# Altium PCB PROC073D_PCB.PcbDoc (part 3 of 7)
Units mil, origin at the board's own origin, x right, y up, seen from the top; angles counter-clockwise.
Board outline 2165.35 x 2695.12 mil, 8 copper layers (Top Layer, L2_GND, L3_SIGNAL 1, L4_SIGNAL 2, L5_SIGNAL 3, L6_SIGNAL 4, L7_GND, Bottom Layer), stack 56.1 mil thick; 414 components, 319 nets, 1353 pads, 1669 vias.
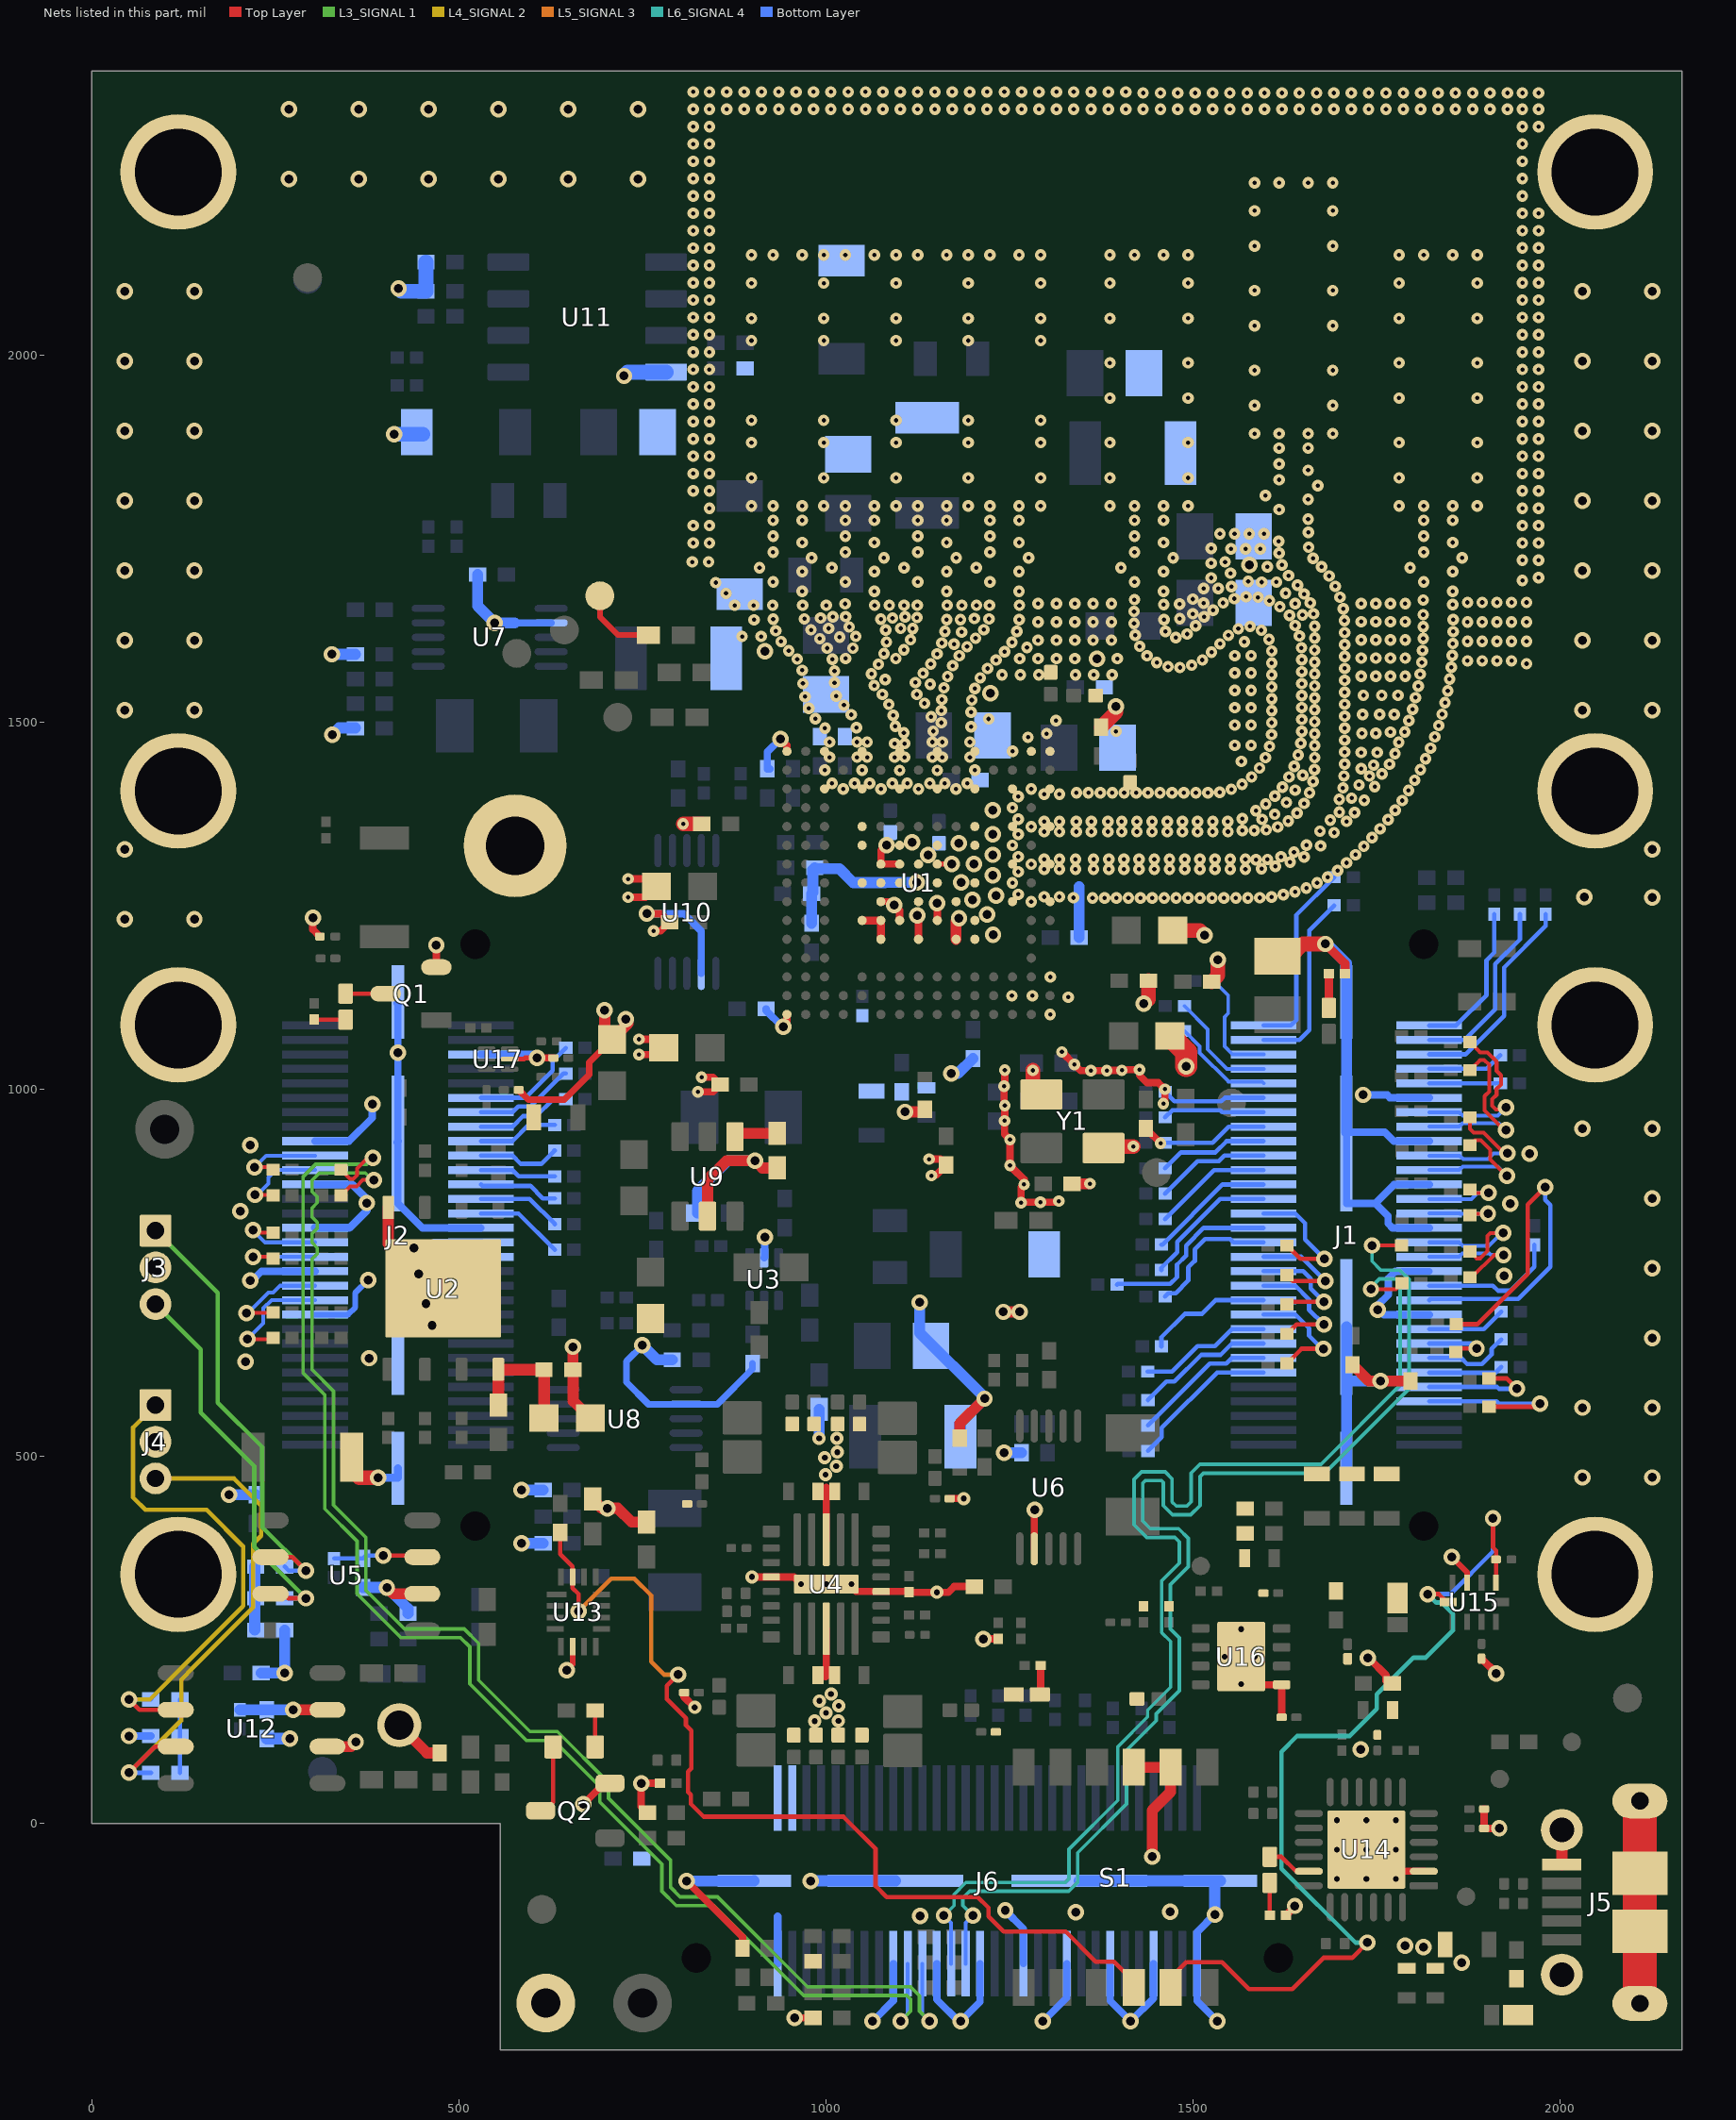
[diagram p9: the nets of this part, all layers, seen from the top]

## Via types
v1: diameter 13.77/15.74 (per signal layer), hole 5.9, Top Layer to L2_GND, tented both sides, 900 vias
v2: diameter 22.4, hole 12.2, Top Layer to Bottom Layer, tented both sides, 509 vias
v3: diameter 13.78/15.75 (per signal layer), hole 5.9, Top Layer to L2_GND, tented both sides, 72 vias
v4: diameter 18, hole 8, Top Layer to Bottom Layer, tented both sides, 71 vias
v5: diameter 22, hole 12.2, Top Layer to Bottom Layer, tented both sides, 57 vias
v6: diameter 25, hole 15, Top Layer to Bottom Layer, tented both sides, 28 vias
v7: diameter 19.68, hole 7.87, Top Layer to Bottom Layer, 16 vias
v8: diameter 13.77/15.74 (per signal layer), hole 5.9, Top Layer to L2_GND, tented top, 15 vias
v9: diameter 13.78/15.75 (per signal layer), hole 5.9, Top Layer to L2_GND, tented top, 1 vias

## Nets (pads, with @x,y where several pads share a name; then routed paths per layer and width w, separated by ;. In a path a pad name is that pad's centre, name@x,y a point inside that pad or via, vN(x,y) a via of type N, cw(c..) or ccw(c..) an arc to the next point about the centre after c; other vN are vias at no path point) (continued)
GND: C1.1 C2.1 C3.1 C4.1 C5.1 C6.2 C7.1 C8.1 C9.1 C10.1 C11.1 C12.1 C13.1 C14.1 C15.1 C16.1 C17.1 C18.1 C19.1 C20.1 C21.1 C22.1 C23.1 C24.1 C25.1 C26.1 C27.1 C28.1 C29.1 C30.2 C31.1 C32.1 C33.1 C34.1 C35.1 C36.1 C37.1 C38.1 C39.1 C40.1 C41.1 C42.1 C43.2 C44.1 C45.1 C46.1 C47.2 C48.2 C49.2 C50.2 C51.2 C52.1 C53.2 C54.2 C55.2 C56.2 C57.1 C58.1 C59.1 C60.2 C61.2 C62.2 C63.1 C64.1 C65.1 C66.2 C67.2 C68.2 C69.2 C70.2 C71.2 C72.2 C73.2 C74.2 C75.2 C76.2 C77.2 C78.2 C79.2 C80.2 C81.2 C82.2 C83.2 C84.2 C85.2 C86.1 C87.1 C88.1 C89.2 C90.2 C91.2 C92.2 C93.2 C94.2 C95.1 C96.1 C97.1 C98.2 C99.2 C100.2 C101.2 C102.2 C103.2 C104.2 D6.2 J1.20 J1.26 J1.32 J1.38 J1.44 J1.50 J1.MP1 J1.MP2 J1.MP3 J1.MP4 J2.19 J2.25 J2.28 J2.30 J2.31 J2.32 J2.37 J2.43 J2.56 J2.MP1 J2.MP2 J2.MP3 J2.MP4 J3.2 J4.2 J5.5 J5.6 J5.7 J5.8 J5.9 J5.10 J5.11 J6.18 J6.24 J6.30 J6.36 J6.42 J6.48 J6.54 J6.60 J6.MP1 J6.MP2 J6.MP3 J6.MP4 pad.TH1 pad.TH2 pad.TH3 pad.TH4 pad.TH5 pad.TH6 pad.TH7 pad.TH8 pad.TH9 Q1.2 Q2.2 R57.2 R71.2 R84.2 R89.1 R95.1 R99.1 R101.1 R103.1 R113.1 R114.1 R116.1 R117.1 R119.2 R120.1 R121.1 R146.1 R147.1 R152.1 R155.1 R158.1 R162.1 R182.1 R194.1 R197.1 R201.1 R205.1 R208.1 R211.1 R212.2 R215.1 S1.8 S1.9 S2.2 TP11.1 TP12.1 U1.A1 U1.A3 U1.A5 U1.A7 U1.A9 U1.A13 U1.A15 U1.B1 U1.B3 U1.B5 U1.B7 U1.B9 U1.B14 U1.C1 U1.C3 U1.C4 U1.C5 U1.C6 U1.C7 U1.C8 U1.C9 U1.C14 U1.E1 U1.E2 U1.E3 U1.E5 U1.E6 U1.E8 U1.E10 U1.E11 U1.F3 U1.F9 U1.F11 U1.G1 U1.G2 U1.G3 U1.G6 U1.G7 U1.G8 U1.G10 U1.H3 U1.H7 U1.H9 U1.H11 U1.J1 U1.J2 U1.J3 U1.J6 U1.J7 U1.J8 U1.J10 U1.K3 U1.K7 U1.K8 U1.K9 U1.K10 U1.K11 U1.L1 U1.L2 U1.L3 U1.L5 U1.L6 U1.L8 U1.L10 U1.M3 U1.N1 U1.N2 U1.N3 U1.R1 U1.R15 U2.4 U2.9 U3.2 U4.4 U4.11 U4.17 U4.24 U4.27 U5.2 U6.7 U7.7 U8.7 U9.2 U10.7 U11.4 U12.2 U13.6 U14.2 U14.25 U15.3 U16.5 U16.9@1565.35,227.53 U17.2 Y1.2 Y1.4 | length 10379
  Top Layer w6.6: U17.2@569.32,1041.14 588.76,1041.14 590.34,1042.72 v2(606.52,1042.72)
  Top Layer w7: U1.J7@1100.38,1305.39 U1.J7@1100.39,1306.64 U1.J7@1100.38,1307.11 ; U1.G7@1151.57,1306.64 U1.G7@1151.57,1306.64 v2(1171.17,1306.65)
  Top Layer w7.87: v2(647.1,209.13) 647.1,209.26 654.91,217.07 U13.6@654.91,241.36 ; v2(1852.08,363.15) 1872.92,342.31 U15.3@1872.92,328.21
  Top Layer w9: C53.2@581.57,999.1 594.54,986.14 643.66,986.14 677.5,1019.98 677.5,1036.69 C70.2@708.74,1067.92 ; U1.K9@1074.8,1255.45 1088.56,1255.46 v2(1093.07,1250.95)
  Top Layer w9.42: U14.25@1765.34,-64.83 U14.2@1814.14,-64.83
  Top Layer w9.8: U6.7@1283.67,374.27 1283.67,427.12 v2@1284.13,427.57
  Top Layer w9.84: v2(301.25,1233.66) 301.25,1217.66 R215.1@310.87,1208.04 ; v2(606.52,1042.72) C52.1@629.01,1042.72
  Top Layer w10: Q1.2@469.47,1166.28 v2(469.47,1196.1) ; v2(669.51,26.57) 698,55.06 Q2.2@705.91,55.06 ; v1(730.59,1261.43) 754.09,1261.43 C17.1@769.1,1276.43 769.09,1276.98 759.39,1286.68 759.14,1286.43 v1(730.59,1286.43) ; v1(745.29,1047.33) 769.99,1047.33 C27.1@779.1,1056.43 767.39,1068.13 v1(745.29,1068.13) ; v2(756.01,1239.14) 775.19,1239.14 C21.1@786.91,1227.43 775,1215.52 v1(765.41,1215.52) ; R182.1@756.92,14.84 748.32,23.44 v2(748.32,55.06) R201.1@774.18,55.06 ; C54.2@806.8,178.5 806.8,172.75 v4(821.22,158.33) ; v2(810.16,-78.01) 886.26,-154.11 R208.1@886.26,-169.67 ; v1(825.59,996.43) 845.91,996.43 C25.1@855.91,1006.43 845.91,1016.43 v1(830.59,1016.43) ; v4(899.33,336.14) 899.49,335.98 U4.4@925.53,335.98 956.23,335.98 v7(966.08,326.14) v7(1000.33,326.14) ; v2(937.97,1477.05) 946.84,1468.18 U1.R1@946.84,1460.18 ; v2(941.65,1085.08) 946.84,1090.27 U1.R15@946.84,1101.91 ; v2(957.39,-264.45) R205.1@982.36,-264.45 ; 999.44,200.24 1000.33,201.13 U4.11@1000.33,265.51 ; 1000.26,458.06 1000.33,457.99 U4.24@1000.33,386.77 ; v7(1000.33,326.14) 1031.3,326.1 1041.1,316.3 U4.17@1075.13,316.3 1111.76,316.3 C68.2@1112.94,315.12 v4(1150.97,315.12) 1166.79,315.12 1174.55,322.88 C57.1@1202.04,322.88 ; v2(1082.37,1332.5) 1074.79,1324.92 U1.K7@1074.8,1306.64 U1.J7@1100.39,1306.64 ; v2(1093.07,1250.95) 1100.38,1243.64 U1.J10@1100.39,1229.86 ; v2(1124.47,1236.55) 1125.97,1235.05 U1.H11@1125.98,1204.27 ; v1(1140.44,904.91) 1155.42,904.91 C16.1@1163.59,896.74 1150.59,883.74 1145.09,883.74 v1(1143.74,882.39) ; U1.G10@1151.57,1229.86 v2(1151.57,1253.45) ; C60.2@1168.45,442.7 v4(1187.66,442.7) ; v2(1214.24,251.58) R194.1@1234.41,251.58 ; v1(1243.49,1025.93) 1243.59,1025.83 1243.59,1005.08 v1(1242.66,1004.15) 1242.66,978.56 v1(1243.49,977.73) 1243.49,957.53 v1(1243.09,957.13) 1243.09,938.93 v1(1250.59,931.43) v1(1250.59,896.43) 1269.74,877.28 v1(1269.74,870.43) 1265.69,866.38 v1(1265.69,845.65) ; v1@1250.2,896.04 1260.59,885.65 ; v1@1266.29,846.25 v1(1291.99,846.25) v1@1315.69,846.25 ; v1(1321.28,1050.86) v1(1338.23,1033.91) 1346.73,1025.41 v1(1360.63,1025.41) v1(1382.33,1025.41) 1382.73,1025.81 v1(1402.93,1025.81) 1403.93,1026.81 v1(1427.03,1026.81) 1427.03,1019.14 1437.24,1008.92 1452.71,1008.92 v1(1461.53,1000.11) 1461.53,982.43 v1(1459.43,980.33) ; Y1.2@1377.91,920.01 Y1.2@1380.15,922.24 ; C32.1@1435.59,946.74 1435.59,946.43 v1(1455.59,926.43) ; U16.9@1565.44,227.53 1565.44,217.05 1593.34,189.15 U16.5@1620.47,189.15 1620.56,189.15 1620.56,145.01 C49.2@1620.47,144.92 ; R99.1@1626.3,-124.7 1638.37,-112.63 v5(1638.37,-111.95) ; v2@1740.36,224.56 1762.57,202.35 C84.2@1762.57,194.49 ; C45.1@1896.13,19.89 C44.1@1896.13,-6.42 v2(1916.7,-6.42)
  Top Layer w10.34: C48.2@1892.6,224.75 1912.71,204.64 v2(1912.71,204.23)
  Top Layer w11: U1.L10@1049.21,1229.86 U1.K10@1074.8,1229.86 U1.K11@1074.8,1204.27
  Top Layer w12: v2(1680,1197.89) 1706.79,1171.1 R212.2@1706.79,1157.61
  Top Layer w15: U12.2@321.29,105.08 353.15,105.08 v2(359.68,111.61) ; v2(402.05,321.68) 410.68,313.05 U5.2@450.43,313.05 ; U2.4@403.88,839.09 403.88,789.85 U2.9@464.88,728.85 ; TP11.1@418.88,134.12 456.66,96.34 R84.2@474.08,96.34 ; C34.1@655.38,618.33 655.76,617.95 655.76,575.53 C35.1@679,552.29 ; C34.1@655.38,618.33 v2(655.42,649.29) ; C43.2@682.22,442.04 694.69,429.57 v2(702.49,429.57) 716.3,429.57 735.36,410.51 R89.1@755.42,410.51 ; v2(698.74,1107.43) 698.74,1077.92 C70.2@708.74,1067.92 730.46,1089.64 727.52,1092.58 v2(727.52,1095.22) ; U9.2@838.74,827.3 838.74,876.81 864.62,902.68 v2(903.51,902.68) 913.39,892.81 C71.2@933.74,892.81 ; v2(1107.62,969.22) 1132.07,969.22 C26.1@1135.59,972.74 ; U1.F11@1177.16,1204.27 1177.15,1228.83 v2(1181.17,1232.85) ; R101.1@1182.13,525.22 1182.13,544.83 v5(1215.98,578.68) ; v5(1241.47,696.95) v5(1263.77,696.95) ; C33.1@1335.28,871.43 v8(1359.59,871.43) ; S1.9@1419.21,76.81 S1.8@1469.21,76.81 1469.21,43.14 1444.06,17.99 v2(1444.06,-45.03) ; R155.1@1717.01,624.91 1739.05,602.87 v2(1754.94,602.87) R152.1@1795.94,602.87
  Top Layer w15.75: J5.5@2001.97,-55.78 J5.10@2001.97,-8.54
  Top Layer w20: S2.2@354.04,498.89 354.04,481.74 364.45,471.33 v2(389.99,471.33) ; v1(805.59,1361.43) C28.1@830.91,1361.43 ; v1(1281.8,1025.71) 1281.8,1004.31 Y1.4@1293.27,992.85 ; C4.1@1374.59,1493.11 1395,1513.52 v2(1395,1521.43) ; Y1.2@1380.15,922.24 v1(1418.59,922.24) ; v2(1432.59,1116.43) 1438.87,1122.7 C5.1@1438.87,1147.84 ; C22.1@1472.09,1216.43 1508.78,1216.43 v2(1515.66,1209.55) ; C14.1@1525.28,1146.43 1533.74,1154.89 v2(1533.74,1176.43) ; C15.1@1615,1181.43 1633.03,1181.43 1649.5,1197.89 v2(1680,1197.89)
  Top Layer w30: C18.1@1468.28,1072.84 1490.59,1050.52 v2(1490.59,1031.43)
  Top Layer w46: J5.6@2108.27,-244.76 J5.7@2108.27,-146.33 J5.8@2108.27,-67.59 J5.9@2108.27,30.83
  Bottom Layer w8: J2.19@304.45,693.16 349.08,693.16 359.13,703.21 359.13,722.48 358.98,722.64 v2(376.73,740.39)
  Bottom Layer w9: v2(750,651.43) 728.28,629.71 728.28,601.13 758.16,571.24 U8.7@809.52,571.24 852.12,571.24 900,619.12 C36.1@900,626.74 ; 1776.59,752.22 J1.26@1821.54,752.22
  Bottom Layer w9.84: J2.56@530.04,1047.49 601.75,1047.49 v2(606.52,1042.72) ; 576.05,1635.09 U7.7@625.74,1635.09
  Bottom Layer w10: v2(50.92,119.38) C42.1@80.8,119.38 ; v2(216.24,739.74) 218.91,739.74 231.39,752.22 J2.25@304.45,752.22 ; J2.37@304.45,870.33 355.06,870.33 375,850.39 v2(375,845.22) ; J2.43@304.45,929.38 350.49,929.38 382.3,961.19 v2(382.3,979.75) ; J2.MP4@417.24,1118.95 415.92,1117.63 417.41,1116.14 417.02,1115.75 v2(417.02,1050.01) 417.02,929.63 417.41,929.24 415.92,927.75 J2.MP3@417.24,926.43 417.24,844.53 450.49,811.27 J2.32@530.04,811.27 ; v2(438.88,783.85) 458.18,783.85 465.92,791.59 J2.30@530.04,791.59 ; v2(445.36,748.27) 468.99,771.9 J2.28@530.04,771.9 ; v2(756.01,1239.14) 806.28,1239.14 830.28,1215.15 U10.7@830.28,1157.77 ; U3.2@915.74,770.56 916.7,771.52 v2(916.7,798.43) ; C63.1@918.43,1109.62 918.42,1107.15 940.5,1085.08 v2(941.65,1085.08) ; R146.1@920.18,1436.29 920.18,1459.26 v2(937.97,1477.05) ; R146.1@923.74,1436.11 R146.1@923.74,1436.29 ; v2(1063.3,-268.91) 1063.85,-268.91 1091.79,-240.97 J6.18@1091.79,-190.65 ; J6.24@1150.84,-190.65 1150.84,-239.14 1180.62,-268.91 v2(1183.58,-268.91) 1209.9,-242.6 J6.30@1209.9,-190.65 ; v2(1244.15,-117.69) v2@1243.53,-117.69 ; J6.36@1268.95,-190.65 1268.95,-143.12 v2@1243.53,-117.69 ; v2(1294.98,-268.91) 1295.8,-268.91 1328.01,-236.7 J6.42@1328.01,-190.65 ; J6.48@1387.06,-190.65 1387.06,-241.08 v2(1414.9,-268.91) 1445.89,-237.92 1445.89,-190.88 J6.54@1446.12,-190.65 ; v2(1529.43,-123.46) 1505.17,-147.73 J6.60@1505.17,-190.65 1505.17,-241.08 v2(1533.01,-268.91) ; v2(1731.57,992.36) 1731.76,992.18 1764.48,992.18 1767.77,988.89 ; 1747.55,844.67 1708.74,844.67 J1.MP3@1708.74,926.43 1708.74,941.68 1760.84,941.68 1773.14,929.38 J1.44@1821.54,929.38 ; 1767.77,988.44 J1.50@1821.54,988.44 ; 1775.49,811.27 J1.32@1821.54,811.27 1771.25,811.27 1765.35,817.18 1765.35,827.25 1747.93,844.67 1773.59,870.33 J1.38@1821.54,870.33 ; 1776.59,752.22 1775.49,752.22 1765.85,742.58 1765.85,720.42 1751.37,705.93 v2(1751.37,699.66) 1753.07,699.66 1759.57,693.16 J1.20@1821.54,693.16 ; v2@1243.53,-117.69 1243.16,-117.33 1243.03,-117.46 1243.26,-117.69 v2@1243.53,-117.69
  Bottom Layer w11: J2.31@304.45,811.27 351.2,811.27 375,835.08 v2(375,845.22) ; v2(389.99,471.33) 417.24,471.33 J2.MP1@417.24,483.91
  Bottom Layer w15: v2(187.4,447.95) C38.1@223.71,447.95 ; C41.1@230.83,205.08 v2(262.88,205.08) C39.1@262.88,263.8 ; v2(326.97,1592.29) R113.1@359.16,1592.31 ; v2(327.89,1483.03) 336.89,1492.03 R114.1@359.16,1492.03 ; C37.1@369.48,321.68 v2(402.05,321.68) 430.92,292.82 R71.2@430.92,285.9 ; J2.MP2@417.24,676.43 419.2,678.39 v2(463.71,678.39) ; C58.1@525.69,1700.76 525.69,1658.11 v2(548.95,1634.85) 549.18,1635.09 576.05,1635.09 ; v2(585.46,381.8) R117.1@614.95,381.8 ; v2(585.46,454.23) R116.1@614.95,454.23 ; v2(750,651.43) 769.68,631.74 C59.1@790.63,631.74 ; v2(810.16,-78.01) 902.07,-78.01 J6.MP1@902.22,-77.86 ; R197.1@825.12,831.43 825.12,861.38 866.42,902.68 v2(903.51,902.68) ; v2(979.45,-77.86) J6.MP2@1094.74,-77.86 ; C10.1@980.28,1266.43 980.28,1226.43 C29.1@980.59,1226.11 ; C10.1@980.28,1266.43 982.13,1268.28 982.13,1298.87 R147.1@984.69,1301.43 985.87,1300.25 1018.4,1300.25 1037.21,1281.43 1079.88,1281.43 1080,1281.55 v2(1123.47,1281.55) ; v4(990.62,524.61) 990.93,524.91 R57.2@990.93,564.13 ; v5(1127.64,709.82) 1127.64,668.43 1215.98,580.09 v5(1215.98,578.68) 1183.23,545.93 C82.2@1183.23,527.14 ; v2(1170.59,1021.43) 1179.68,1021.43 C9.1@1200,1041.74 ; v2(1242.56,505.12) R103.1@1266.47,505.12 ; C6.2@1344.69,1206.43 1344.68,1276.11 ; J6.MP3@1344.74,-77.86 J6.MP4@1531.53,-77.86 ; v2(1529.43,-123.46) 1529.43,-79.96 J6.MP4@1531.53,-77.86 ; J6.MP4@1537.26,-77.86 J6.MP4@1531.53,-77.86 ; v2(1680,1197.89) 1682.3,1197.89 1708.74,1171.45 J1.MP4@1708.74,1118.95 J1.MP3@1708.74,941.68 ; J1.MP1@1708.74,483.91 J1.MP2@1708.74,602.87 ; J1.MP2@1708.74,676.43 J1.MP2@1708.74,602.87 ; v2(1754.94,602.87) J1.MP2@1708.74,602.87
  Bottom Layer w16: C40.1@238.73,115.71 v2(269.94,115.71)
  Bottom Layer w20: v2(411.86,1892.06) C64.1@451.17,1892.06 ; v5(418,2090.43) 422,2086.43 R158.1@455.32,2086.43 C65.1@455.32,2126.43 ; v5(725,1971.43) 730,1976.43 U11.4@782.28,1976.43
  other v1: 1317.09,847.65 1305.31,1101.71 1330,1125.43 1253.08,1127.29 1281.08,1127.29 1305.58,1152.88 1279.52,1255.45 1337.05,1260.84 1362.97,1260.44 1379.24,1260.44 1395.5,1260.44 1411.77,1260.44 1428.03,1260.44 1444.3,1260.44 1460.56,1260.44 1476.83,1260.44 1493.09,1260.44 1509.36,1260.44 1525.62,1260.44 1541.89,1260.44 1558.15,1260.44 1574.42,1260.44 1590.68,1260.81 1606.91,1261.87 1297.24,1262.06 1317.9,1262.06 1622.9,1264.85 1261.81,1265.48 1638.67,1268.83 1654.07,1274.05 1253.93,1281.05 1668.78,1281 1683.02,1288.85 1261.81,1296.19 1696.54,1297.89 1297.24,1299.61 1317.9,1299.61 1279.52,1306.43 1709,1308.34 1297.23,1313.24 1317.9,1313.24 1261.8,1316.66 1720.95,1319.37 1732.45,1330.87 1673.43,1331.34 1253.93,1332.23 1743.69,1342.64 1261.8,1347.37 1297.24,1350.79 1317.9,1350.79 1566.95,1352.42 1583.22,1352.42 1599.46,1353.21 1754.61,1354.69 1279.51,1357.61 1615.23,1357.22 1297.23,1364.42 1317.9,1364.42 1547,1364.43 1708.91,1364.8 1629.44,1365.11 1261.8,1367.84 1765.24,1367 1567,1368.43 1641.4,1376.14 1719.83,1376.86 1585.34,1379.41 1774.93,1380.06 1253.93,1383.41 1598.86,1388.45 1651.14,1389.16 1784.62,1393.13 1698.87,1394.89 1715.74,1396.43 1261.8,1398.55 1611.09,1399.18 1297.24,1401.97 1317.9,1401.97 1341,1403.6 1357.27,1403.6 1373.53,1403.6 1389.8,1403.6 1406.06,1403.6 1422.33,1403.6 1438.59,1403.6 1454.86,1403.6 1471.12,1403.6 1487.39,1403.6 1503.65,1403.6 1519.92,1403.6 1658.5,1403.67 1536.16,1404.5 1793.23,1406.93 1279.51,1408.79 1551.94,1408.41 1023.62,1409 1074.8,1409 1125.98,1409 1177.16,1409 1621.65,1411.54 1725.74,1414.43 1566.61,1415.44 1008.26,1416.67 1038.97,1416.67 1059.44,1416.67 1090.15,1416.67 1110.62,1416.67 1141.33,1416.67 1161.8,1416.67 1192.51,1416.67 1663.26,1419.22 1801.59,1420.88 1579.54,1425.3 1630.47,1425.21 1705.38,1426.71 1740,1426.43 1049.21,1434.59 1100.39,1434.38 1151.57,1434.38 1202.75,1434.59 1665.28,1435.36 1809.41,1435.14 1728.74,1436.59 1590.31,1437.49 1637.61,1439.82 1745.74,1441.43 1767.26,1442.68 1706.22,1442.95 1565.74,1446.43 1816.36,1449.84 1598.46,1451.56 1665.42,1451.62 1004.84,1452.1 1042.39,1452.1 1056.02,1452.1 1093.57,1452.1 1107.2,1452.1 1144.75,1452.1 1158.38,1452.1 1195.93,1452.1 1642.96,1455.18 1774.81,1457.08 1728.74,1458.59 1750.74,1458.59 1706.22,1459.22 1254.13,1460.39 1823.27,1464.57 1603.95,1466.87 1665.42,1467.89 1556.74,1468.38 1578.91,1468.38 1093.57,1470.76 1107.2,1470.76 1646.44,1471.07 1004.84,1472.76 1042.39,1472.76 1056.02,1472.76 1144.75,1472.76 1158.38,1472.76 1195.93,1472.76 1706.22,1475.48 1275.08,1479.29 1828.85,1479.84 1606.59,1482.92 1300.58,1484.29 1665.42,1484.15 1729.74,1484.54 1748.74,1484.54 1106,1485.43 1768.74,1486.43 1788.14,1486.75 1146.02,1487.51 1647.72,1487.29 998.62,1491.59 1706.22,1491.75 1041.46,1492.37 1197.56,1493.53 1094.35,1494.43 1834.33,1495.16 1556.74,1495.94 1578.91,1495.94 1157.08,1499.15 1607,1499.18 1665.42,1500.42 1313.11,1501.98 1793.62,1502.07 1647.79,1503.55 985.62,1504.59 1221.58,1504.29 1143.22,1507.22 1706.22,1508.01 1091.55,1508.99 1034.33,1510.11 1730.74,1510.48 1753.74,1510.48 1773.74,1510.48 1838.99,1510.74 1197.56,1513.73 1157.08,1515.69 1607,1515.45 1665.42,1516.68 1798.77,1517.49 976.62,1518.59 1556.74,1519.56 1578.91,1519.56 1647.79,1519.81 1024.45,1523.03 1085.58,1524.12 1706.22,1524.27 1134.21,1525.41 1842.94,1526.52 1157.74,1530.56 1198.59,1529.96 1607,1531.71 1665.42,1532.95 1802.72,1533.27 971.62,1534.59 1013.89,1535.4 1647.79,1536.08 1731.74,1536.43 1756.74,1536.43 1778.74,1536.43 1076.69,1537.74 1123.56,1537.71 1706.22,1540.54 1846.71,1542.34 1556.74,1543.18 1578.91,1543.18 1202.74,1545.69 1160.66,1546.56 1607,1547.98 1065.72,1549.75 1665.42,1549.21 1806.61,1549.06 1141.94,1551.41 968.62,1552.59 1647.79,1552.34 1011.62,1553.59 1121.92,1553.89 1706.22,1556.8 1080.65,1557.78 1849.1,1558.43 1209.99,1560.25 1165.67,1562.04 1728.74,1562.37 1748.74,1562.37 1768.74,1562.37 1788.74,1562.37 1239.74,1564.43 1264.74,1564.43 1289.74,1564.43 1339.74,1564.43 1364.74,1564.43 1389.74,1564.43 1607,1564.24 1061.86,1565.55 1665.42,1565.48 1809,1565.15 1132.26,1566.45 1556.74,1566.81 1578.91,1566.81 1647.79,1568.61 1011.62,1569.59 967.62,1570.59 1220.05,1573.03 1706.22,1573.07 1481.97,1574.3 1851.49,1574.52 1465.75,1575.49 1172.66,1576.72 1497.94,1577.4 1071.51,1578.64 1142.67,1578.95 1953.98,1579.48 1607,1580.51 1450.42,1580.94 1665.42,1581.74 1811.38,1581.24 1873.55,1583.42 1893.53,1583.42 1913.54,1583.42 1933.52,1583.42 1231.62,1584.46 1512.54,1584.56 1647.79,1584.87 960.84,1585.7 1008.62,1585.59 1026.62,1586.59 1095.15,1586.55 1263.74,1586.43 1288.74,1586.43 1313.74,1586.43 1338.74,1586.43 1396.74,1586.43 1728.74,1587.14 1748.74,1587.14 1768.74,1587.14 1788.74,1587.14 1706.22,1589.33 1181.53,1590.35 1437.1,1590.27 1556.74,1590.43 1578.91,1590.43 1852.78,1590.73 1151.18,1592.8 1078.92,1593.12 1243.21,1595.87 1524.97,1595.05 1607,1596.77 949.34,1597.21 1812.41,1597.47 1106.16,1598.52 1665.42,1598.01 1001.62,1600.59 1036.62,1600.59 1273.74,1601.43 1647.44,1601.13 1192.14,1602.68 1427.08,1603.08 1706.22,1605.6 1174.3,1606.06 1536.47,1606.55 1157.62,1607.74 1853.58,1606.97 1253.2,1608.7 938.95,1609.73 1082.34,1609.02 1569.74,1609.43 1873.55,1609.92 1893.53,1609.92 1913.54,1609.92 1933.52,1609.92 1953.98,1609.92 1288.74,1611.43 1313.74,1611.43 1338.74,1611.43 1363.74,1611.43 1388.74,1611.43 1728.74,1611.9 1748.74,1611.9 1768.74,1611.9 1788.74,1611.9 1115.1,1612.11 1603.27,1612.6 991.62,1613.59 1813.21,1613.72 1203.64,1614.18 1665.42,1614.27 1018.62,1615.59 1476.3,1615.11 885.86,1616.59 911.74,1616.59 1040.62,1616.59 1644.78,1617.18 1420.97,1618.15 1547.97,1618.05 1491.83,1619.92 1706.22,1621.86 1184.62,1622.59 1162.03,1623.4 1259.92,1623.52 1462.28,1623.35 1854.01,1623.23 931.71,1624.29 979.62,1625.59 1081.19,1625.24 1215.08,1625.74 1592.84,1625.08 1003.62,1627.59 1101.66,1627.59 1561.5,1627.09 1031.62,1629.59 1577.44,1630.31 1665.42,1630.54 1813.21,1629.98 1503.49,1631.26 1419.51,1634.35 1288.74,1636.43 1313.74,1636.43 1338.74,1636.43 1363.74,1636.43 1388.74,1636.43 1728.74,1636.66 1748.74,1636.66 1768.74,1636.66 1788.74,1636.66 1873.55,1636.43 1893.53,1636.43 1913.54,1636.43 1933.52,1636.43 1953.98,1636.43 1706.05,1638.13 902.2,1639.31 1164.35,1639.49 1263,1639.49 1460.31,1639.5 1854.01,1639.5 928.08,1640.14 970.62,1640.59 1074.71,1640.16 1222.11,1640.41 1481.65,1640.69 992.62,1641.59 1090.66,1641.59 1202.2,1641 1009.47,1643.3 1026.62,1643.59 1107.51,1643.3 1515,1643.43 1648.83,1645.81 1813.21,1646.25 1499.62,1647.36 1419.51,1650.61 1527,1652.43 1704.44,1654.31 1617.97,1657.05 875.62,1659 901.49,1659 927.37,1659 968.17,1659 1000.3,1659 1066.23,1659 1086.21,1658.99 1106.22,1659 1124.23,1659 1165.03,1659 1185,1658.99 1205.02,1659 1222.65,1659 1263.45,1659 1459.84,1659.92 1853.54,1659.92 1481.64,1660.7 1288.74,1661.43 1313.74,1661.43 1338.74,1661.43 1363.74,1661.43 1388.74,1661.43 1638.99,1661.44 1728.74,1661.43 1748.74,1661.43 1768.74,1661.43 1788.74,1661.43 1514.23,1661.98 1540.83,1662.35 1659.55,1662.31 1893.53,1662.92 1933.52,1662.92 1953.98,1662.92 1873.55,1662.93 1913.54,1662.93 1603.91,1665.22 1420.03,1666.68 1813.21,1666.25 1499.61,1667.38 1556.03,1668.12 1588.33,1669.88 1572.09,1670.73 1700.01,1669.96 863.94,1675.21 1625.84,1675.45 967.55,1677.89 1065.98,1677.89 1164.41,1677.89 1262.84,1677.89 1459.7,1677.91 1853.4,1677.91 1514.22,1681.99 1534.24,1682 1552,1684.43 1693.57,1684.9 849.84,1689.89 1593.39,1690.6 1613.4,1690.61 1575,1691.43 1948.27,1692.74 1524.57,1696.34 1970.43,1696.68 1685.24,1698.86 1550.77,1702.66 967.55,1704.92 1065.98,1704.92 1164.41,1704.92 1262.84,1704.92 1459.69,1704.93 1853.4,1704.93 909.5,1710.12 1007.93,1710.12 1106.36,1710.12 1204.79,1710.12 1401.65,1710.14 1795.35,1710.14 1601,1711.43 1674.91,1711.43 1620.8,1714.14 1524.56,1716.35 818.11,1718.08 840.28,1718.08 1543.5,1718.07 1948.27,1720.3 1970.43,1720.3 1663.37,1722.89 980.54,1723.51 1078.97,1723.51 1177.4,1723.51 1275.83,1723.51 1472.69,1723.52 1866.39,1723.52 1616.87,1729.92 928,1731.46 1026.43,1731.46 1124.86,1731.46 1223.29,1731.46 1420.15,1731.48 1813.85,1731.48 1551.47,1735.76 1571.48,1735.77 1591.46,1735.76 1524.57,1736.33 1657.16,1737.92 819.09,1743.91 841.26,1743.91 1948.27,1743.92 1970.43,1743.92 967.56,1744.45 1065.99,1744.45 1164.42,1744.45 1262.85,1744.45 1459.69,1744.48 1853.4,1744.48 1616.36,1746.18 927.99,1753.09 1026.42,1753.09 1124.85,1753.09 1223.28,1753.09 1420.14,1753.1 1813.84,1753.1 1536.37,1756.34 1556.35,1756.33 1576.36,1756.34 1596.34,1756.33 1656.69,1758.35 819.09,1767.53 841.26,1767.53 1948.27,1767.54 1970.43,1767.54 928,1774.69 967.55,1774.69 1026.43,1774.69 1065.98,1774.69 1124.86,1774.69 1164.41,1774.69 1223.29,1774.69 1262.84,1774.69 1420.15,1774.7 1459.69,1774.7 1813.85,1774.7 1853.4,1774.7 1656.55,1776.33 841.26,1791.15 1948.27,1791.17 1970.43,1791.17 898.55,1794.38 928,1794.38 967.55,1794.38 997,1794.38 1026.43,1794.38 1065.98,1794.38 1095.43,1794.38 1124.86,1794.38 1164.41,1794.38 1193.86,1794.38 1223.29,1794.38 1262.84,1794.38 1292.29,1794.38 1386.65,1794.39 1420.15,1794.39 1459.69,1794.39 1493.18,1794.39 1780.35,1794.39 1813.85,1794.39 1853.4,1794.39 1886.88,1794.39 1656.55,1803.36 1598.5,1808.56 819.09,1814.77 841.26,1814.77 1948.27,1814.79 1970.43,1814.79 1669.54,1821.95 1617,1829.91 898.55,1832.53 996.98,1832.54 1095.41,1832.54 1193.84,1832.54 1292.27,1832.54 1386.65,1832.54 1493.18,1832.54 1780.35,1832.54 1886.88,1832.54 819.09,1838.4 841.26,1838.4 1948.27,1838.41 1970.43,1838.41 1656.55,1842.9 1616.99,1851.53 819.09,1862.02 841.26,1862.02 1948.27,1862.03 1970.43,1862.03 1617,1873.13 1656.55,1873.13 898.55,1880.56 996.97,1880.56 1095.4,1880.56 1193.83,1880.56 1292.26,1880.56 1386.65,1880.57 1493.18,1880.57 1780.35,1880.57 1886.88,1880.57 819.09,1885.64 841.26,1885.64 1948.27,1885.66 1970.43,1885.66 1583.5,1892.81 1617,1892.81 1656.55,1892.81 1690.03,1892.81 819.09,1909.26 841.26,1909.26 1948.27,1909.28 1970.43,1909.28 898.55,1910.83 996.97,1910.83 1095.4,1910.83 1193.83,1910.83 1292.26,1910.83 1583.5,1930.96 1690.03,1930.96 819.09,1932.88 841.26,1932.88 1948.27,1932.9 1970.43,1932.9 1386.65,1941.12 1493.18,1941.12 1780.35,1941.12 1886.88,1941.12 819.09,1956.51 841.26,1956.51 1948.27,1956.52 1970.43,1956.52 1583.5,1979 1690.03,1979 819.09,1980.13 841.26,1980.13 1948.27,1980.14 1970.43,1980.14 1386.65,1989.15 1493.18,1989.15 1780.35,1989.15 1886.88,1989.15 819.09,2003.75 841.26,2003.75 1948.27,2003.77 1970.43,2003.77 898.55,2019.42 996.97,2019.42 1095.4,2019.42 1193.83,2019.42 1292.26,2019.42 819.09,2027.37 841.26,2027.37 1948.27,2027.39 1970.43,2027.39 1583.5,2039.55 1690.03,2039.55 898.55,2049.69 996.97,2049.69 1095.4,2049.69 1193.83,2049.69 1292.26,2049.69 1386.65,2049.7 1493.18,2049.7 1780.35,2049.7 1886.88,2049.7 819.09,2050.99 841.26,2050.99 1948.27,2051.01 1970.43,2051.01 819.09,2074.62 841.26,2074.62 1948.27,2074.63 1970.43,2074.63 1583.5,2087.58 1690.03,2087.58 898.55,2097.72 996.97,2097.72 1095.4,2097.72 1193.83,2097.72 1292.26,2097.72 1386.65,2097.74 1493.2,2097.74 1780.35,2097.74 1886.9,2097.74 819.09,2098.24 841.26,2098.24 1948.27,2098.25 1970.43,2098.25 819.09,2121.86 841.26,2121.86 1948.27,2121.88 1970.43,2121.88 898.55,2135.87 928,2135.87 967.56,2135.87 996.97,2135.87 1026.43,2135.87 1065.99,2135.87 1095.4,2135.87 1124.86,2135.87 1164.42,2135.87 1193.83,2135.87 1223.29,2135.87 1262.85,2135.87 1292.26,2135.87 1386.65,2135.89 1420.15,2135.89 1459.69,2135.89 1493.2,2135.89 1780.35,2135.89 1813.85,2135.89 1853.4,2135.89 1886.9,2135.89 819.09,2145.48 841.26,2145.48 1948.27,2145.5 1970.43,2145.5 1583.5,2148.13 1690.03,2148.13 819.09,2169.1 841.26,2169.1 1948.27,2169.12 1970.43,2169.12 819.09,2192.73 841.26,2192.73 1948.27,2192.74 1970.43,2192.74 1583.5,2196.16 1690.05,2196.16 819.09,2216.35 841.26,2216.35 1948.27,2216.36 1583.5,2234.31 1617,2234.31 1656.55,2234.31 1690.05,2234.31 819.09,2239.97 841.26,2239.97 1948.27,2239.99 819.09,2263.59 841.26,2263.59 1948.27,2263.61 819.09,2287.21 841.26,2287.21 1948.27,2287.23 819.09,2310.84 841.26,2310.84 1948.27,2310.85 1970.43,2310.85 819.09,2334.46 841.26,2334.46 864.88,2334.46 888.5,2334.46 912.13,2334.46 935.75,2334.46 959.37,2334.46 982.99,2334.46 1006.61,2334.46 1030.24,2334.46 1053.86,2334.46 1077.48,2334.46 1101.1,2334.46 1124.72,2334.46 1148.35,2334.46 1171.97,2334.46 1195.59,2334.46 1219.21,2334.46 1242.83,2334.46 1266.46,2334.46 1290.08,2334.46 1313.7,2334.46 1337.32,2334.46 1360.94,2334.46 1384.57,2334.46 1408.19,2334.46 1431.81,2334.46 1455.43,2334.46 1479.05,2334.46 1502.68,2334.46 1526.3,2334.46 1549.92,2334.46 1573.54,2334.46 1597.16,2334.46 1620.79,2334.46 1644.41,2334.46 1668.03,2334.46 1691.65,2334.46 1715.28,2334.46 1738.9,2334.46 1762.52,2334.46 1786.14,2334.46 1809.76,2334.46 1833.39,2334.46 1857.01,2334.46 1880.63,2334.46 1904.25,2334.46 1927.87,2334.46 1948.27,2334.46 1970.43,2334.46 1431.81,2356.62 1455.43,2356.62 1479.05,2356.62 1502.68,2356.62 1526.3,2356.62 1549.92,2356.62 1573.54,2356.62 1597.16,2356.62 1620.79,2356.62 1644.41,2356.62 1668.03,2356.62 1691.65,2356.62 1715.28,2356.62 1738.9,2356.62 1762.52,2356.62 1786.14,2356.62 1809.76,2356.62 1833.39,2356.62 1857.01,2356.62 1880.63,2356.62 1904.25,2356.62 1927.87,2356.62 1948.27,2356.62 1970.43,2356.62 819.09,2358.08 841.26,2358.08 864.88,2358.08 888.5,2358.08 912.13,2358.08 935.75,2358.08 959.37,2358.08 982.99,2358.08 1006.61,2358.08 1030.24,2358.08 1053.86,2358.08 1077.48,2358.08 1101.1,2358.08 1124.72,2358.08 1148.35,2358.08 1171.97,2358.08 1195.59,2358.08 1219.21,2358.08 1242.83,2358.08 1266.46,2358.08 1290.08,2358.08 1313.7,2358.08 1337.32,2358.08 1360.94,2358.08 1384.57,2358.08 1408.19,2358.08
  other v2: 1865.55,-189.16 1813.78,-167.95 1788.41,-166.32 1128.1,-125.61 1339.94,-120.35 1468.86,-119.68 1728,101.21 1737.94,225.83 1284.15,427.57 2030,471.43 2125,471.43 2030,566.43 2125,566.43 209.88,628.89 378.08,633.88 2125,661.43 455.36,708.27 1923.34,745.97 2125,756.43 202.55,833.82 1931.64,844.3 2125,851.43 1958.02,912.59 215.88,923.8 2030,946.43 2125,946.43 1227.47,1210.3 45,1231.43 140,1231.43 1219.57,1238.1 1199.37,1257.7 2032.46,1261.51 2125,1261.43 1231.37,1263.6 1184.17,1281.55 1226.87,1291.25 1201.17,1306.65 1139.07,1319.1 1227.07,1319.25 45,1326.43 2125,1326.43 1180.97,1335.25 1117.07,1336.43 1227.07,1347.25 1226.87,1380.1 45,1516.43 140,1516.43 2030,1516.43 2125,1516.43 1224,1539.43 1369.04,1586.23 916.93,1596.43 45,1611.43 140,1611.43 2030,1611.43 2125,1611.43 45,1706.43 140,1706.43 2030,1706.43 2125,1706.43 1576.32,1713.88 45,1801.43 140,1801.43 2030,1801.43 2125,1801.43 45,1896.43 140,1896.43 2030,1896.43 2125,1896.43 45,1991.43 140,1991.43 2030,1991.43 2125,1991.43 45,2086.43 140,2086.43 2030,2086.43 2125,2086.43 269,2239.43 364,2239.43 459,2239.43 554,2239.43 649,2239.43 744,2239.43 269,2334.43 364,2334.43 459,2334.43 554,2334.43 649,2334.43 744,2334.43
  other v3: 1339.76,1299.62 1364.4,1299.62 1385.07,1299.62 1405.74,1299.62 1426.41,1299.62 1447.08,1299.62 1467.75,1299.62 1488.42,1299.62 1509.09,1299.62 1529.75,1299.62 1550.42,1299.62 1571.09,1299.62 1593,1300.43 1612,1303.43 1632,1309.43 1585.71,1312.49 1339.76,1313.25 1364.4,1313.25 1385.07,1313.25 1405.74,1313.25 1426.41,1313.25 1447.07,1313.25 1467.74,1313.25 1488.41,1313.25 1509.08,1313.25 1529.75,1313.25 1550.42,1313.25 1571.09,1313.25 1601.22,1313 1619.68,1316.62 1651,1316.43 1637.28,1322.92 1654.18,1332.51 1692,1349.43 1340.67,1350.79 1361.34,1350.79 1383.87,1350.79 1402.68,1350.79 1423.35,1350.79 1444.02,1350.79 1464.69,1350.79 1485.36,1350.79 1506.03,1350.79 1526.68,1350.79 1547.33,1350.79 1672.56,1351.47 1340.67,1364.43 1361.34,1364.43 1383.87,1364.43 1402.68,1364.43 1423.35,1364.43 1444.02,1364.43 1464.69,1364.43 1485.36,1364.43 1506.03,1364.43 1526.68,1364.43 1686.76,1366.47 1594,1367.43 1611,1374.43 1627,1390.43 1733,1393.43 1639,1407.43 1704,1410.43 1649,1427.43 1757,1429.43 1780,1472.43 1639,1631.43 1631,1645.43 1664,1647.43 1651,1674.43 1642,1686.43 1630,1699.43
  other v4: 984.8,139.62 1017.02,140.1 999.94,150.72 1017.5,160.4 991.22,167.11 1006.94,176.66 999.53,475.13 1013.98,486.93 998.34,498.47 1015.34,505.85 1014.69,524.54
  other v7: 1695.81,-75.3 1735.81,-75.3 1775.81,-75.3 1695.81,-35.3 1735.81,-35.3 1775.81,-35.3 1695.81,4.7 1735.81,4.7 1775.81,4.71 1565.35,190.13 1542.8,227.53 1583.76,227.53 1565.35,264.94 1034.58,326.14
  other v8: 1747.21,1411.98 998.5,1434.59 1395,1487.43 1118.1,1627.23 1183.1,1639.6 1123.89,1642.25 1026.18,1660.99 928,1690.9 1026.43,1690.9 1124.86,1690.9 1223.29,1690.9 1420.15,1690.91 1813.85,1690.91 1617,1789.33
  other v9: 1699,1377.43
MON_1V: R72.1 TP2.1 | length 115.1
  Top Layer w8: TP2.1@692.27,1671.93 692.27,1643.16 717,1618.43 R72.1@758.5,1618.43 ; R72.1@758.5,1617.63 R72.1@768.36,1617.63
MUX_IN_1: R88.1 S1.4 U13.15 | length 1326.1
  Top Layer w6: R88.1@638.24,396.67 638.24,366.84 654.91,350.16 U13.15@654.91,335.85 654.91,321.02 663.21,312.73 v2(663.21,289.49) ; v2(798.8,202.93) 783.45,187.59 783.45,169.57 809.36,143.66 809.36,134.04 816.49,126.91 816.49,75.14 812.26,70.91 812.26,43.07 816.1,39.22 816.1,26.9 833.42,9.58 1023.78,9.58 1067.56,-34.2 1067.56,-84.84 1082.61,-99.9 1206.81,-99.9 1221.31,-114.39 1221.31,-126.24 1242.12,-147.06 1326.39,-147.06 1367.15,-187.81 1392.01,-187.81 1419.21,-215.01 S1.4@1419.21,-223.19
  L5_SIGNAL 3 w6: v2(663.21,289.49) 707.44,333.72 720.26,333.72 ; 720.28,333.74 739.17,333.74 762.13,310.78 762.13,220.37 779.57,202.93 v2(798.8,202.93)
MUX_IN_2: R100.1 S1.5 U15.1 U15.5 | length 1311.8
  Top Layer w6: S1.5@1469.21,-223.19 1469.21,-209.79 1490.23,-188.77 1539.33,-188.77 1575.85,-225.29 1634.88,-225.29 1677.62,-182.55 1716.61,-182.55 v2(1737.23,-161.93) ; v2(1819.25,312.65) 1834.44,312.65 1845.45,301.64 U15.5@1847.33,301.64 ; v2(1908.32,416.05) 1908.32,375.82 1912.29,371.86 R100.1@1912.29,359.82 U15.1@1912.29,328.21
  L6_SIGNAL 4 w6: v2(1737.23,-161.93) 1721.11,-161.93 1620.38,-61.2 1620.38,98.06 1641.78,119.47 1713.41,119.47 1750.11,156.18 1750.11,176.03 1800.18,226.1 1816.77,226.1 1854.06,263.38 1854.06,285.5 1838.47,301.09 1830.81,301.09 v2(1819.25,312.65)
  Bottom Layer w6: v2(1819.25,312.65) 1850.14,312.65 1908.32,370.82 v2(1908.32,416.05)
NetC34_2: C34.2 C35.2 R43.1 U2.8 | length 176.8
  Top Layer w16: R43.1@553.88,570.07 U2.8@553.88,618.61 554.16,618.33 C34.2@616.01,618.33 C35.2@616.01,552.29
NetC37_2: C37.2 R69.1 U5.3 | length 122.7
  Top Layer w6: v2(397.28,365.05) 448.44,365.05 U5.3@450.43,363.05
  Bottom Layer w6: R69.1@330.22,361.05 C37.2@369.48,361.05 373.48,365.05 v2(397.28,365.05)
NetC39_2: C39.2 R68.1 R79.2 | length 86.2
  Bottom Layer w15: C39.2@222.27,263.8 222.27,306.93 R79.2@222.27,350.05
NetC40_2: C40.2 R82.1 U12.3 | length 119.3
  Top Layer w15: v2(274.44,155.08) U12.3@321.29,155.08
  Bottom Layer w15: R82.1@201.99,155.08 C40.2@238.73,155.08 v2(274.44,155.08)
NetC42_2: C42.2 R81.1 R86.2 | length 100
  Bottom Layer w6: R81.1@120.17,69.38 C42.2@120.17,119.38 R86.2@120.17,169.38
NetC71_1: C71.1 U9.4 | length 59.5
  Top Layer w15: U9.4@876.14,935.56 880.63,940.05 C71.1@933.74,940.05
NetD1_2: D1.2 L9.2
NetD2_2: D2.2 L10.2
NetD3_1: D3.1 R172.1 | length 49.6
  Top Layer w6: D3.1@685.62,104.57 R172.1@685.62,154.18
NetD3_2: D3.2 Q2.3 | length 97.2
  Top Layer w6: Q2.3@611.42,17.66 616.94,17.66 628.53,29.26 D3.2@628.53,104.57
NetD4_1: D4.1 U14.17 | length 61.4
  Top Layer w6: D4.1@1604.25,-45.11 1620.08,-45.11 1639.8,-64.83 U14.17@1657.48,-64.83
NetD4_2: D4.2 R99.2 | length 44.2
  Top Layer w6: R99.2@1604.25,-124.7 D4.2@1604.25,-80.55
NetD5_1: D5.1 R141.2 | length 43
  Top Layer w6: R141.2@302.97,1094.83 D5.1@345.96,1094.83
NetD5_2: D5.2 Q1.3 | length 54.5
  Top Layer w6: D5.2@345.96,1130.26 Q1.3@400.43,1130.26
NetD6_1: D6.1 R174.2 | length 39.9
  Top Layer w10: D6.1@1291.17,175.99 1292.34,177.16 R174.2@1292.34,215.41
NetD7_2: D7.2 R212.1 | length 46.9
  Top Layer w12: D7.2@1684.74,1110.71 R212.1@1684.74,1157.61
NetJ1_8: J1.8 R17.2 | length 222.8
  Top Layer w6: R17.2@1902.85,567.81 1968.09,567.81 v2(1972.11,571.83)
  Bottom Layer w6: J1.8@1821.54,575.05 1912.94,575.05 1916.16,571.83 v2(1972.11,571.83)
NetJ1_10: J1.10 R15.2 | length 164.4
  Top Layer w6: R15.2@1902.85,606.18 1927.07,606.18 v2(1941,592.25)
  Bottom Layer w6: J1.10@1821.54,594.74 1913.93,594.74 1916.42,592.25 v2(1941,592.25)
NetJ1_11: J1.11 R5.2 | length 209.2
  Bottom Layer w6: R5.2@1438.43,507.55 1457.25,526.38 1457.25,539.05 1532.62,614.42 J1.11@1595.95,614.42
NetJ1_12: J1.12 R42.2 | length 101.4
  Bottom Layer w6: J1.12@1821.54,614.42 1822.07,613.89 1911.35,613.89 R42.2@1919.39,621.93
NetJ1_13: J1.13 R8.1 | length 195.6
  Bottom Layer w6: R8.1@1438.43,542.19 1522.65,626.42 1545.04,626.42 1552.73,634.11 J1.13@1595.95,634.11
NetJ1_14: J1.14 R13.1 | length 119.5
  Bottom Layer w6: J1.14@1821.54,634.11 1864.76,634.11 1872.98,625.89 1893.3,625.89 1906.36,638.95 1906.36,646.47 R13.1@1919.37,659.47
NetJ1_15: J1.15 R6.1 | length 189.4
  Bottom Layer w6: R6.1@1438.43,576.84 1463.54,601.95 1474.5,601.95 1510.97,638.42 1537.36,638.42 1552.73,653.79 J1.15@1595.95,653.79
NetJ1_16: J1.16 R10.1 | length 97.3
  Top Layer w6: R10.1@1857.66,642.24 1862.44,647.02 v2(1885.85,647.02)
  Bottom Layer w6: J1.16@1821.54,653.79 1879.08,653.79 v2(1885.85,647.02)
NetJ1_17: J1.17 R4.1 | length 181.9
  Bottom Layer w6: R4.1@1437.96,615.63 1471.21,615.63 1506,650.42 1529.67,650.42 1552.73,673.48 J1.17@1595.95,673.48
NetJ1_18: J1.18 R31.1 | length 107.6
  Bottom Layer w6: J1.18@1821.54,673.48 1895.68,673.48 R31.1@1919.37,697.17
NetJ1_19: J1.19 R7.2 | length 164.5
  Top Layer w6: R7.2@1627.75,626.86 1647.63,646.74 v2(1677.37,646.74)
  Bottom Layer w6: J1.19@1595.95,693.16 1639.17,693.16 1657.79,674.55 1657.79,664.31 1675.36,646.74 v2(1677.37,646.74)
NetJ1_21: J1.21 R9.2 | length 172.4
  Bottom Layer w6: R9.2@1456.74,650 1456.74,662.28 1488.64,694.18 1511.91,694.18 1530.57,712.85 J1.21@1595.95,712.85
NetJ1_22: J1.22 R36.1 | length 548.2
  Top Layer w6: R36.1@1858.34,680.05 1886.85,680.05 1955.49,748.68 1955.49,842.88 v2(1979.15,866.55)
  Bottom Layer w6: J1.22@1821.54,712.85 1823.13,714.43 1942.66,714.43 1986.3,758.07 1986.3,842.36 1979.15,849.51 v2(1979.15,866.55)
NetJ1_23: J1.23 R11.2 | length 167.6
  Top Layer w6: R11.2@1627.75,666.94 1640.62,679.81 v2(1677.99,679.81)
  Bottom Layer w6: J1.23@1595.95,732.53 1639.17,732.53 1657.77,713.93 1657.77,700.02 v2(1677.99,679.81)
NetJ1_24: J1.24 R16.1 | length 188.9
  Bottom Layer w6: J1.24@1821.54,732.53 1908.2,732.53 1914.97,725.77 1931.7,725.77 1964.4,758.46 R16.1@1964.4,788.15
NetJ1_25: J1.25 R12.1 | length 158.9
  Top Layer w6: R12.1@1627.75,707.02 1631.32,710.58 v2(1677.97,710.58)
  Bottom Layer w6: J1.25@1595.95,752.22 1649.9,752.22 1659.9,742.21 1659.9,728.65 v2(1677.97,710.58)
NetJ1_27: J1.27 R18.2 | length 153.5
  Top Layer w6: R18.2@1627.75,747.1 1635.87,738.98 v2(1680.1,738.98)
  Bottom Layer w6: J1.27@1595.95,771.9 1647.19,771.9 v2(1680.1,738.98)
NetJ1_28: J1.28 R22.1 | length 162
  Top Layer w5.2: R22.1@1876.78,744.08 1879.66,744.08 1909.95,774.37 v2(1922.48,774.37)
  Bottom Layer w5.2: J1.28@1821.54,771.9 1862.24,771.9 1866.82,776.48 1903.3,776.48 1905.41,774.37 v2(1922.48,774.37)
NetJ1_29: J1.29 R19.2 | length 188.3
  Bottom Layer w6: R19.2@1461.74,717.75 1466.33,722.34 1476.31,722.34 1493.34,739.37 1493.34,757.38 1502.29,766.33 1502.29,782.13 1516.22,796.06 1550.46,796.06 1554.93,791.59 J1.29@1595.95,791.59
NetJ1_30: J1.30 R24.1 | length 183
  Top Layer w5.2: R24.1@1876.78,779.08 1886.08,769.78 1890.94,769.78 1900.68,779.52 1900.68,800.29 1904.6,804.21 v2(1921.93,804.21)
  Bottom Layer w5.2: J1.30@1821.54,791.59 1862.23,791.59 1867.14,786.68 1902.28,786.68 v2@1919.81,804.21
NetJ1_31: J1.31 R20.2 | length 249.6
  Bottom Layer w6: R20.2@1396.27,733.93 1397.36,735.02 1468.67,735.02 1477.98,744.32 1477.98,761.09 1490.29,773.4 1490.29,787.1 1514.46,811.27 J1.31@1595.95,811.27
NetJ1_33: J1.33 R21.2 | length 180
  Top Layer w6: R21.2@1627.75,787.18 1645.81,769.12 v2(1678.81,769.12)
  Bottom Layer w6: J1.33@1595.95,830.96 1639.17,830.96 1652.51,817.61 1652.51,795.42 v2(1678.81,769.12)
NetJ1_34: J1.34 R30.1 | length 105.2
  Top Layer w5.2: R30.1@1876.78,828.55 1878.84,830.61 v2(1901.28,830.61)
  Bottom Layer w5.2: J1.34@1821.54,830.96 1862.96,830.96 1863.3,830.61 v2(1901.28,830.61)
NetJ1_35: J1.35 R23.2 | length 189
  Bottom Layer w6: R23.2@1456.74,753.93 1456.74,756.82 1478.17,778.26 1478.17,791.96 1536.86,850.64 J1.35@1595.95,850.64
NetJ1_36: J1.36 R32.1 | length 111.9
  Top Layer w5.2: R32.1@1876.78,863.55 1881.32,859.01 v2(1902.42,859.01)
  Bottom Layer w5.2: J1.36@1821.54,850.64 1879.04,850.64 1887.41,859.01 v2(1902.42,859.01)
NetJ1_37: J1.37 R26.2 | length 173.1
  Bottom Layer w6: R26.2@1456.74,788.57 1458.21,788.57 1539.97,870.33 J1.37@1595.95,870.33
NetJ1_39: J1.39 R27.2 | length 161.9
  Bottom Layer w6: R27.2@1461.74,823.21 1528.53,890.01 J1.39@1595.95,890.01
NetJ1_40: J1.40 R33.1 | length 194.2
  Top Layer w5.2: R33.1@1876.78,923.9 1883.63,930.75 1891.38,930.75 1904.53,917.6 1904.53,904.43 1926.82,882.14 v2(1927.34,882.14)
  Bottom Layer w5.2: J1.40@1821.54,890.01 1862.22,890.01 1866.96,894.75 1914.72,894.75 v2(1927.34,882.14)
NetJ1_41: J1.41 R28.2 | length 155.7
  Bottom Layer w6: R28.2@1461.74,857.86 1505.89,902.01 1535.09,902.01 1542.78,909.7 J1.41@1595.95,909.7
NetJ1_42: J1.42 R35.1 | length 191.9
  Top Layer w5.2: R35.1@1876.78,961.88 1876.78,946.32 1882.15,940.95 1895.6,940.95 1923.75,912.8 v2(1927.77,912.8)
  Bottom Layer w5.2: J1.42@1821.54,909.7 1862.89,909.7 1867.64,904.95 1901.14,904.95 1908.98,912.8 v2(1927.77,912.8)
NetJ1_43: J1.43 R60.1 | length 149.5
  Bottom Layer w6: R60.1@1461.74,892.5 1483.27,914.04 1530.15,914.04 1545.49,929.38 J1.43@1595.95,929.38
NetJ1_45: J1.45 R61.1 | length 143.3
  Bottom Layer w6: R61.1@1461.74,927.14 1526.28,927.14 1548.21,949.07 J1.45@1595.95,949.07
NetJ1_46: J1.46 R39.1 | length 249.7
  Top Layer w5.2: R39.1@1876.78,1026.09 1890.67,1039.98 1896.38,1039.98 1902.94,1033.42 1902.94,996.74 1896.93,990.73 1896.93,971.28 1923.98,944.22 v2(1925.87,944.22)
  Bottom Layer w5.2: J1.46@1821.54,949.07 1862.17,949.07 1866.91,953.81 1916.28,953.81 v2(1925.87,944.22)
NetJ1_47: J1.47 R62.1 | length 139.5
  Bottom Layer w6: R62.1@1461.74,961.79 1471.58,971.63 1536.45,971.63 1539.33,968.75 J1.47@1595.95,968.75
NetJ1_48: J1.48 R41.1 | length 247.9
  Top Layer w5.2: R41.1@1876.78,1064.07 1890.67,1050.18 1900.6,1050.18 1913.14,1037.64 1913.14,1024.82 1918.98,1018.99 1918.98,1006.33 1913.14,1000.49 1913.14,992.51 1907.13,986.5 1907.13,977.39 1912.28,972.24 1922.88,972.24 v2(1925.87,975.22)
  Bottom Layer w5.2: J1.48@1821.54,968.75 1862.37,968.75 1867.11,964.01 1914.65,964.01 v2(1925.87,975.22)
NetJ1_49: J1.49 R63.1 | length 141.5
  Bottom Layer w6: R63.1@1461.74,996.43 1474.53,983.63 1538.17,983.63 1542.98,988.44 J1.49@1595.95,988.44
NetJ1_51: J1.51 R64.1 | length 142.9
  Bottom Layer w5: R64.1@1487.99,1079.43 1508.75,1058.67 1508.75,1049.7 1547.74,1010.71 1547.74,1010.43 1593.64,1010.43 J1.51@1595.95,1008.12
NetJ1_52: J1.52 R58.1 | length 96.8
  Bottom Layer w6: J1.52@1821.54,1008.12 R58.1@1918.31,1008.12
NetJ1_53: J1.53 R34.2 | length 159.5
  Bottom Layer w5: R34.2@1487.99,1113.43 1519.75,1081.67 1519.75,1054.26 1546.2,1027.81 J1.53@1595.95,1027.81
NetJ1_54: J1.54 R59.1 | length 104.5
  Bottom Layer w6: J1.54@1821.54,1027.81 1899.75,1027.81 R59.1@1918.31,1046.36
NetJ1_55: J1.55 R37.2 | length 157.2
  Bottom Layer w5: R37.2@1527.99,1147.43 1547.7,1127.72 1547.7,1103.27 1542.62,1098.19 1542.62,1058.31 1553.44,1047.49 J1.55@1595.95,1047.49
NetJ1_56: J1.56 R65.2 | length 285.4
  Bottom Layer w6: J1.56@1821.54,1047.49 1870.75,1047.49 1923.4,1100.14 1923.4,1165.75 1980,1222.34 R65.2@1980,1238.44
NetJ1_57: J1.57 R38.2 | length 251.4
  Bottom Layer w5.98: J1.57@1595.95,1067.18 1644.39,1067.18 1657.95,1080.74 1657.95,1216.43 R38.2@1691.95,1250.43
NetJ1_58: J1.58 R66.1 | length 250.6
  Bottom Layer w6: J1.58@1821.54,1067.18 1869.68,1067.18 1911.4,1108.9 1911.4,1170.72 1945,1204.31 R66.1@1945,1238.44
NetJ1_59: J1.59 R40.2 | length 263.5
  Bottom Layer w5.98: J1.59@1595.95,1086.86 1633.14,1086.86 1640.48,1094.2 1640.48,1237.34 R40.2@1691.95,1288.81
NetJ1_60: J1.60 R67.1 | length 209.6
  Bottom Layer w6: J1.60@1821.54,1086.86 1858.01,1086.86 1899.4,1128.26 1899.4,1175.69 1910,1186.28 R67.1@1910,1238.44
NetJ2_21: J2.21 R137.1 | length 162
  Top Layer w5.2: v2(211.97,659.7) 245.27,659.7 R137.1@247.01,661.43
  Bottom Layer w5.2: v2(211.97,659.7) 234,681.73 234,701.71 245.14,712.85 J2.21@304.45,712.85
NetJ2_23: J2.23 R136.1 | length 145.2
  Top Layer w5.2: v2(211,695.43) 246.01,695.43 R136.1@247.01,696.43
  Bottom Layer w5.2: v2(211,695.43) 213.3,695.43 240.92,723.05 247.13,723.05 256.61,732.53 J2.23@304.45,732.53
NetJ2_27: J2.27 R135.1 | length 113
  Top Layer w5.2: v2(219.68,771.9) 244.78,771.9 R135.1@247.01,769.68
  Bottom Layer w5.2: v2(219.68,771.9) J2.27@304.45,771.9
NetJ2_29: J2.29 R134.1 | length 120.3
  Top Layer w5.2: v2(219.68,808.06) 223.06,804.68 R134.1@247.01,804.68
  Bottom Layer w5.2: v2(219.68,808.06) 236.15,791.59 J2.29@304.45,791.59
NetJ2_34: J2.34 R132.2 | length 121.2
  Bottom Layer w6: J2.34@530.04,830.96 581.22,830.96 R132.2@630.75,781.43
NetJ2_36: J2.36 R130.2 | length 114.9
  Bottom Layer w6: J2.36@530.04,850.64 596.54,850.64 R130.2@630.75,816.43
NetJ2_38: J2.38 R129.2 | length 108.5
  Bottom Layer w6: J2.38@530.04,870.33 531.93,868.43 597.51,868.43 614.51,851.43 R129.2@630.75,851.43
NetJ2_39: J2.39 R133.1 | length 127.8
  Top Layer w5.2: v2(222.53,856.17) 241.22,856.17 244.45,852.94 R133.1@247.01,855.5
  Bottom Layer w5.2: v2(222.53,856.17) 225.33,856.17 240.92,871.76 240.92,880.24 250.7,890.01 J2.39@304.45,890.01
NetJ2_40: J2.40 R128.2 | length 104.3
  Bottom Layer w6: J2.40@530.04,890.01 573.26,890.01 581.84,881.43 R128.2@630.75,881.43
NetJ2_41: J2.41 R131.1 | length 115.2
  Top Layer w5.2: v2(222.1,893.88) 243.63,893.88 R131.1@247.01,890.5
  Bottom Layer w5.2: v2(222.1,893.88) 237.92,909.7 J2.41@304.45,909.7
NetJ2_42: J2.42 R127.2 | length 112.8
  Bottom Layer w6: J2.42@530.04,909.7 573.26,909.7 584.45,898.51 612.26,898.51 630.18,916.43 R127.2@630.75,916.43
NetJ2_44: J2.44 R126.2 | length 109.8
  Bottom Layer w6: J2.44@530.04,929.38 573.26,929.38 595.3,951.43 R126.2@630.75,951.43
NetJ2_46: J2.46 R125.2 | length 131.2
  Bottom Layer w6: J2.46@530.04,949.07 573.25,949.07 587.62,963.43 605.44,963.43 628.44,986.43 R125.2@645.75,986.43
NetJ2_48: J2.48 R124.2 | length 137.5
  Bottom Layer w6: J2.48@530.04,968.75 573.25,968.75 580.94,976.44 597.69,976.44 642.68,1021.43 R124.2@645.75,1021.43
NetJ2_50: J2.50 R140.2 | length 151.3
  Bottom Layer w6: J2.50@530.04,988.44 590.5,988.44 627.7,1025.63 627.7,1038.37 R140.2@645.75,1056.43
NetJ3_1: J3.1 R79.1 U5.6 | length 634.3
  Top Layer w6: U5.6@243.74,363.05 273.06,363.05 v2(291.64,344.48)
  L3_SIGNAL 1 w6: J3.1@87.13,807.43 171.9,722.66 171.9,573.37 232.48,512.79 232.48,403.64 v2(291.64,344.48)
  Bottom Layer w6: R79.1@262.88,350.05 268.45,344.48 v2(291.64,344.48)
NetJ3_3: J3.3 R68.2 U5.7 | length 564.4
  Top Layer w6: U5.7@243.74,313.05 261.63,313.05 267.76,306.93 v2(291.64,306.93)
  L3_SIGNAL 1 w6: J3.3@87.13,707.43 148.68,645.87 148.68,559.93 221.48,487.13 221.48,377.09 v2(291.64,306.93)
  Bottom Layer w6: R68.2@262.88,306.93 v2(291.64,306.93)
NetJ4_1: J4.1 R86.1 U12.6 | length 705
  Top Layer w6: v2(50.92,169.38) 65.23,155.08 U12.6@114.6,155.08
  L4_SIGNAL 2 w6: v2(50.92,169.38) 79.62,169.38 128.22,217.98 206.44,296.23 206.44,377.51 156.68,427.28 73.34,427.28 56.48,444.14 56.48,539.43 J4.1@87.13,570.09
  Bottom Layer w6: v2(50.92,169.38) R86.1@80.8,169.38
NetJ4_3: J4.3 R81.2 U12.7 | length 705.6
  Top Layer w6: v2(50.92,69.38) 86.62,105.08 U12.7@114.6,105.08
  L4_SIGNAL 2 w6: v2(50.92,69.38) 122.21,140.67 122.21,196.42 139.22,213.43 220,294.23 220,381.34 230.87,392.21 230.87,433.09 193.87,470.09 J4.3@87.13,470.09
  Bottom Layer w6: v2(50.92,69.38) R81.2@80.8,69.38
NetJ6_1: J6.1 J6.2 J6.3 R122.2 | length 64.2
  Bottom Layer w10.98: J6.2@934.31,-190.65 934.31,-126.46
NetJ6_20: J6.20 R217.1 | length 1933.2
  Top Layer w5.2: R217.1@339.59,890.5 351.99,878.1 356.65,878.1 361.67,883.11 361.67,892.32 375.85,906.5 v2(382.93,906.5)
  L3_SIGNAL 1 w4.8: v2(382.93,906.5) 374.44,898.01 305.1,898.01 288.19,881.1 288.19,613.34 317.58,583.94 317.58,428.76 361.48,384.86 361.48,312.96 421.14,253.31 502.34,253.31 514.99,240.65 514.99,190.49 592.1,113.38 629.39,113.38 691.92,50.85 691.92,29.64 776.56,-55 776.56,-91.93 796.24,-111.61 847.36,-111.61 969.67,-233.92 1110.17,-233.92 1115.31,-239.07 1115.31,-255.17 v2(1101.58,-268.91)
  Bottom Layer w5.2: v2(1101.58,-268.91) 1111.47,-259.02 J6.20@1111.47,-190.65
NetJ6_22: J6.22 R218.1 | length 1921.1
  Top Layer w5.2: R218.1@339.59,855.5 351.99,867.9 360.88,867.9 369.46,876.48 v2(384.51,876.48)
  L3_SIGNAL 1 w4.8: v2(384.51,876.48) 382.41,876.48 372.87,886.01 310.07,886.01 300.19,876.13 300.19,860.69 307.35,853.53 307.35,845.46 300.19,838.29 300.19,825.91 307.35,818.75 307.35,810.68 300.19,803.51 300.19,791.13 307.35,783.97 307.35,775.9 300.19,768.73 300.19,618.31 329.58,588.91 329.58,433.74 373.48,389.84 373.48,317.93 426.11,265.31 507.31,265.31 526.99,245.62 526.99,195.46 597.07,125.38 634.36,125.38 703.92,55.82 703.92,34.61 788.56,-50.03 788.56,-86.96 801.21,-99.61 852.33,-99.61 974.64,-221.92 1115.14,-221.92 1127.31,-234.1 1127.31,-255.17 v2(1141.05,-268.91)
  Bottom Layer w5.2: J6.22@1131.16,-190.65 1131.16,-259.02 v2(1141.05,-268.91)
NetJ6_26: J6.26 R219.1 | length 1663.4
  Top Layer w5.2: v5(1742.18,727.86) 1775.92,727.86 R219.1@1784.28,736.22
  L6_SIGNAL 4 w4.8: v2(1160.63,-125.14) 1174.37,-111.4 1174.37,-96.25 1190.55,-80.07 1325.69,-80.07 1330.87,-74.89 1330.87,-34.65 1397.23,31.72 1397.23,104.8 1437.73,145.3 1437.73,154.46 1469.16,185.89 1469.16,248.1 1457.02,260.23 1457.02,330.67 1481.28,354.93 1481.28,383.6 1475.19,389.68 1436.74,389.68 1419.54,406.89 1419.54,468.9 1429.77,479.13 1461.75,479.13 1471.27,469.61 1471.27,438.16 1476.93,432.5 1491.56,432.5 1497.31,438.25 1497.31,477.56 1509.07,489.33 1674.09,489.33 1781.88,597.12 1781.88,736.28 1776.33,741.82 1753.48,741.82 1742.18,730.52 v5(1742.18,727.86)
  Bottom Layer w5.2: v2(1160.63,-125.14) 1170.53,-135.04 J6.26@1170.53,-190.65
NetJ6_28: J6.28 R220.1 | length 1695.7
  Top Layer w5.2: v5(1743.62,787.38) R220.1@1783.86,787.38
  L6_SIGNAL 4 w4.8: v2(1200.11,-125.14) 1186.37,-111.4 1186.37,-101.22 1195.52,-92.07 1330.66,-92.07 1342.87,-79.86 1342.87,-39.62 1409.23,26.75 1409.23,99.83 1449.73,140.33 1449.73,149.49 1481.16,180.92 1481.16,253.07 1469.02,265.21 1469.02,325.7 1493.28,349.96 1493.28,388.57 1480.17,401.68 1441.71,401.68 1431.54,411.86 1431.54,463.93 1434.74,467.13 1456.78,467.13 1459.27,464.64 1459.27,433.18 1471.96,420.5 1496.53,420.5 1509.31,433.28 1509.31,472.59 1514.04,477.33 1679.06,477.33 1793.88,592.15 1793.88,741.25 1781.3,753.82 1755.57,753.82 1743.62,765.77 v5(1743.62,787.38)
  Bottom Layer w5.2: J6.28@1190.21,-190.65 1190.21,-135.04 v2(1200.11,-125.14)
